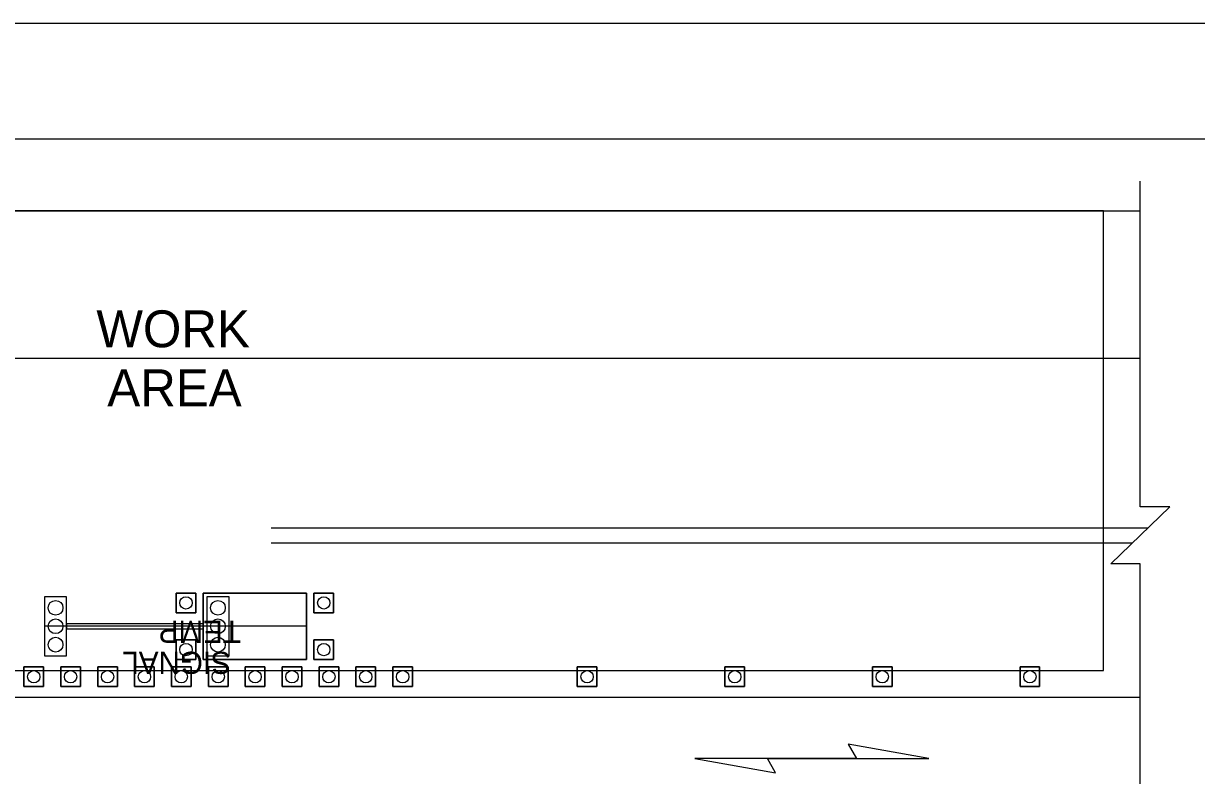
# Model space of a CAD drawing. Extents: x 99977 to 100176, y 99905 to 100011.
# Drawn here: x 100101.998 to 100105.178, y 100008.648 to 100010.687 of the extents above; entities that cross this region are included whole.
import ezdxf

# ---------------------------------------------------------------- set-up
doc = ezdxf.new("R2010")
doc.units = 0
for name, color, linetype in [('RD_ED_ShoulderPavedEdge', 7, 'Continuous'), ('RD_MK_LineDblYellowCenter', 7, 'Continuous'), ('RD_MK_LineEdgeWhite', 7, 'Continuous'), ('SH_GI_PlotLimits', 7, 'Continuous'), ('SH_GI_SheetBorder', 7, 'Continuous'), ('TR_WZ_TempSignal', 7, 'Continuous'), ('TR_WZ_TrafficCone', 7, 'Continuous'), ('TR_WZ_WorkAreaLabel', 7, 'Continuous'), ('TR_WZ_WorkZoneDetails', 7, 'Continuous')]:
    doc.layers.add(name, color=color, linetype=linetype)

msp = doc.modelspace()

# ---------------------------------------------------------------- linework, layer by layer
at = {"layer": 'RD_ED_ShoulderPavedEdge'}
msp.add_line((100100.225, 100010.1795), (100105.025, 100010.1795), dxfattribs=at)
at = {"layer": 'RD_MK_LineDblYellowCenter'}
for p, q in [((100102.6688, 100009.3195), (100105.0457, 100009.3195)), ((100102.6688, 100009.2795), (100105.0043, 100009.2795))]:
    msp.add_line(p, q, dxfattribs=at)
at = {"layer": 'RD_MK_LineEdgeWhite'}
for p, q in [((100100.225, 100009.7795), (100105.025, 100009.7795)), ((100105.025, 100008.8595), (100100.225, 100008.8595))]:
    msp.add_line(p, q, dxfattribs=at)
at = {"layer": 'SH_GI_PlotLimits'}
msp.add_lwpolyline([(100099.0625, 99999.6875), (100116.0625, 99999.6875), (100116.0625, 100010.6875), (100099.0625, 100010.6875)], close=True, dxfattribs=at)
at = {"layer": 'SH_GI_SheetBorder'}
msp.add_line((100100, 100010.375), (100115.75, 100010.375), dxfattribs=at)
at = {"layer": 'TR_WZ_TempSignal'}
for p, q in [((100102.1148, 100009.1328), (100102.0548, 100009.1328)), ((100102.0548, 100009.1328), (100102.0548, 100008.9729)), ((100102.1148, 100008.9729), (100102.1148, 100009.1328)), ((100102.485, 100009.1429), (100102.7652, 100009.1429)), ((100102.485, 100008.9628), (100102.485, 100009.1429)), ((100102.7652, 100009.1429), (100102.485, 100009.1429)), ((100102.485, 100009.1429), (100102.485, 100009.0595)), ((100102.555, 100009.1328), (100102.495, 100009.1328)), ((100102.495, 100009.1328), (100102.495, 100008.9729)), ((100102.555, 100008.9729), (100102.555, 100009.1328)), ((100102.7652, 100009.1429), (100102.7652, 100008.9628)), ((100102.7652, 100008.9628), (100102.7652, 100009.1429)), ((100102.7652, 100009.0529), (100102.0548, 100009.0529)), ((100102.485, 100009.0595), (100102.1148, 100009.0595)), ((100102.1148, 100009.0595), (100102.1148, 100009.0462)), ((100102.1148, 100009.0462), (100102.485, 100009.0462)), ((100102.485, 100009.0462), (100102.485, 100009.0595)), ((100102.485, 100009.0595), (100102.485, 100009.0462)), ((100102.485, 100009.0462), (100102.485, 100008.9628)), ((100102.0548, 100008.9729), (100102.1148, 100008.9729)), ((100102.495, 100008.9729), (100102.555, 100008.9729)), ((100102.7652, 100008.9628), (100102.485, 100008.9628)), ((100102.485, 100008.9628), (100102.7652, 100008.9628))]:
    msp.add_line(p, q, dxfattribs=at)
for points in [[(100102.1148, 100009.1328), (100102.0548, 100009.1328), (100102.0548, 100008.9729), (100102.1148, 100008.9729), (100102.1148, 100009.1328)], [(100102.555, 100009.1328), (100102.495, 100009.1328), (100102.495, 100008.9729), (100102.555, 100008.9729), (100102.555, 100009.1328)]]:
    msp.add_lwpolyline(points, dxfattribs=at)
for centre in [(100102.0848, 100009.1028), (100102.0848, 100009.1028), (100102.525, 100009.1028), (100102.525, 100009.1028), (100102.0848, 100009.0529), (100102.0848, 100009.0529), (100102.525, 100009.0529), (100102.525, 100009.0529), (100102.0848, 100009.0029), (100102.0848, 100009.0029), (100102.525, 100009.0029), (100102.525, 100009.0029)]:
    msp.add_circle(centre, 0.02, dxfattribs=at)
at = {"layer": 'TR_WZ_TrafficCone'}
for points in [[(100102.4117, 100009.1429), (100102.465, 100009.1429), (100102.465, 100009.0896), (100102.4117, 100009.0896), (100102.4117, 100009.1429)], [(100102.4117, 100009.0896), (100102.465, 100009.0896), (100102.465, 100009.1429), (100102.4117, 100009.1429), (100102.4117, 100009.0896)], [(100102.7852, 100009.1429), (100102.8385, 100009.1429), (100102.8385, 100009.0896), (100102.7852, 100009.0896), (100102.7852, 100009.1429)], [(100102.7852, 100009.0896), (100102.8385, 100009.0896), (100102.8385, 100009.1429), (100102.7852, 100009.1429), (100102.7852, 100009.0896)], [(100102.4117, 100009.0161), (100102.465, 100009.0161), (100102.465, 100008.9628), (100102.4117, 100008.9628), (100102.4117, 100009.0161)], [(100102.4117, 100008.9628), (100102.465, 100008.9628), (100102.465, 100009.0161), (100102.4117, 100009.0161), (100102.4117, 100008.9628)], [(100102.7852, 100009.0161), (100102.8385, 100009.0161), (100102.8385, 100008.9628), (100102.7852, 100008.9628), (100102.7852, 100009.0161)], [(100102.7852, 100008.9628), (100102.8385, 100008.9628), (100102.8385, 100009.0161), (100102.7852, 100009.0161), (100102.7852, 100008.9628)], [(100101.999, 100008.9428), (100102.0523, 100008.9428), (100102.0523, 100008.8895), (100101.999, 100008.8895), (100101.999, 100008.9428)], [(100101.999, 100008.8895), (100102.0523, 100008.8895), (100102.0523, 100008.9428), (100101.999, 100008.9428), (100101.999, 100008.8895)], [(100102.099, 100008.9428), (100102.1523, 100008.9428), (100102.1523, 100008.8895), (100102.099, 100008.8895), (100102.099, 100008.9428)], [(100102.099, 100008.8895), (100102.1523, 100008.8895), (100102.1523, 100008.9428), (100102.099, 100008.9428), (100102.099, 100008.8895)], [(100102.199, 100008.9428), (100102.2523, 100008.9428), (100102.2523, 100008.8895), (100102.199, 100008.8895), (100102.199, 100008.9428)], [(100102.199, 100008.8895), (100102.2523, 100008.8895), (100102.2523, 100008.9428), (100102.199, 100008.9428), (100102.199, 100008.8895)], [(100102.299, 100008.9428), (100102.3523, 100008.9428), (100102.3523, 100008.8895), (100102.299, 100008.8895), (100102.299, 100008.9428)], [(100102.299, 100008.8895), (100102.3523, 100008.8895), (100102.3523, 100008.9428), (100102.299, 100008.9428), (100102.299, 100008.8895)], [(100102.399, 100008.9428), (100102.4523, 100008.9428), (100102.4523, 100008.8895), (100102.399, 100008.8895), (100102.399, 100008.9428)], [(100102.399, 100008.8895), (100102.4523, 100008.8895), (100102.4523, 100008.9428), (100102.399, 100008.9428), (100102.399, 100008.8895)], [(100102.499, 100008.9428), (100102.5523, 100008.9428), (100102.5523, 100008.8895), (100102.499, 100008.8895), (100102.499, 100008.9428)], [(100102.499, 100008.8895), (100102.5523, 100008.8895), (100102.5523, 100008.9428), (100102.499, 100008.9428), (100102.499, 100008.8895)], [(100102.599, 100008.9428), (100102.6523, 100008.9428), (100102.6523, 100008.8895), (100102.599, 100008.8895), (100102.599, 100008.9428)], [(100102.599, 100008.8895), (100102.6523, 100008.8895), (100102.6523, 100008.9428), (100102.599, 100008.9428), (100102.599, 100008.8895)], [(100102.699, 100008.9428), (100102.7523, 100008.9428), (100102.7523, 100008.8895), (100102.699, 100008.8895), (100102.699, 100008.9428)], [(100102.699, 100008.8895), (100102.7523, 100008.8895), (100102.7523, 100008.9428), (100102.699, 100008.9428), (100102.699, 100008.8895)], [(100102.799, 100008.9428), (100102.8523, 100008.9428), (100102.8523, 100008.8895), (100102.799, 100008.8895), (100102.799, 100008.9428)], [(100102.799, 100008.8895), (100102.8523, 100008.8895), (100102.8523, 100008.9428), (100102.799, 100008.9428), (100102.799, 100008.8895)], [(100102.899, 100008.9428), (100102.9523, 100008.9428), (100102.9523, 100008.8895), (100102.899, 100008.8895), (100102.899, 100008.9428)], [(100102.899, 100008.8895), (100102.9523, 100008.8895), (100102.9523, 100008.9428), (100102.899, 100008.9428), (100102.899, 100008.8895)], [(100102.999, 100008.9428), (100103.0523, 100008.9428), (100103.0523, 100008.8895), (100102.999, 100008.8895), (100102.999, 100008.9428)], [(100102.999, 100008.8895), (100103.0523, 100008.8895), (100103.0523, 100008.9428), (100102.999, 100008.9428), (100102.999, 100008.8895)], [(100103.499, 100008.9428), (100103.5523, 100008.9428), (100103.5523, 100008.8895), (100103.499, 100008.8895), (100103.499, 100008.9428)], [(100103.499, 100008.8895), (100103.5523, 100008.8895), (100103.5523, 100008.9428), (100103.499, 100008.9428), (100103.499, 100008.8895)], [(100103.899, 100008.9428), (100103.9523, 100008.9428), (100103.9523, 100008.8895), (100103.899, 100008.8895), (100103.899, 100008.9428)], [(100103.899, 100008.8895), (100103.9523, 100008.8895), (100103.9523, 100008.9428), (100103.899, 100008.9428), (100103.899, 100008.8895)], [(100104.299, 100008.9428), (100104.3523, 100008.9428), (100104.3523, 100008.8895), (100104.299, 100008.8895), (100104.299, 100008.9428)], [(100104.299, 100008.8895), (100104.3523, 100008.8895), (100104.3523, 100008.9428), (100104.299, 100008.9428), (100104.299, 100008.8895)], [(100104.699, 100008.9428), (100104.7523, 100008.9428), (100104.7523, 100008.8895), (100104.699, 100008.8895), (100104.699, 100008.9428)], [(100104.699, 100008.8895), (100104.7523, 100008.8895), (100104.7523, 100008.9428), (100104.699, 100008.9428), (100104.699, 100008.8895)]]:
    msp.add_lwpolyline(points, dxfattribs=at)
for centre in [(100102.4384, 100009.1163), (100102.8119, 100009.1163), (100102.4384, 100008.9895), (100102.8119, 100008.9895), (100102.0257, 100008.9161), (100102.1257, 100008.9161), (100102.2257, 100008.9161), (100102.3257, 100008.9161), (100102.4257, 100008.9161), (100102.5257, 100008.9161), (100102.6257, 100008.9161), (100102.7257, 100008.9161), (100102.8257, 100008.9161), (100102.9257, 100008.9161), (100103.0257, 100008.9161), (100103.5257, 100008.9161), (100103.9257, 100008.9161), (100104.3257, 100008.9161), (100104.7257, 100008.9161)]:
    msp.add_circle(centre, 0.0167, dxfattribs=at)
at = {"layer": 'TR_WZ_WorkZoneDetails'}
for p, q in [((100104.2556, 100008.6945), (100104.0144, 100008.6945)), ((100104.0144, 100008.6945), (100104.2556, 100008.6945))]:
    msp.add_line(p, q, dxfattribs=at)
msp.add_lwpolyline([(100105.025, 100008.3395), (100105.025, 100009.2221), (100104.945, 100009.2221), (100105.105, 100009.3769), (100105.025, 100009.3769), (100105.025, 100010.2595)], dxfattribs=at)
msp.add_lwpolyline([(100105.025, 100008.3395), (100105.025, 100009.2221), (100104.945, 100009.2221), (100105.105, 100009.3769), (100105.025, 100009.3769), (100105.025, 100010.2595)], dxfattribs=at)
for points in [[(100100.325, 100010.1795), (100100.325, 100008.9328), (100104.925, 100008.9328), (100104.925, 100010.1795)], [(100104.4521, 100008.6945), (100104.2333, 100008.733), (100104.2556, 100008.6945)], [(100103.8179, 100008.6945), (100104.0367, 100008.6559), (100104.0144, 100008.6945)]]:
    msp.add_lwpolyline(points, close=True, dxfattribs=at)

# ---------------------------------------------------------------- texts
at = {"layer": 'TR_WZ_TempSignal'}
for s, p in [('TEMP', (100102.5872, 100009.0678)), ('SIGNAL', (100102.5601, 100008.9838))]:
    msp.add_text(s, height=0.06, rotation=180, dxfattribs=at).set_placement(p)
at = {"layer": 'TR_WZ_WorkAreaLabel'}
for s, p in [('WORK', (100102.1955, 100009.8095)), ('AREA', (100102.2251, 100009.6495))]:
    msp.add_text(s, height=0.1, dxfattribs=at).set_placement(p)

doc.saveas('drawing.dxf')
